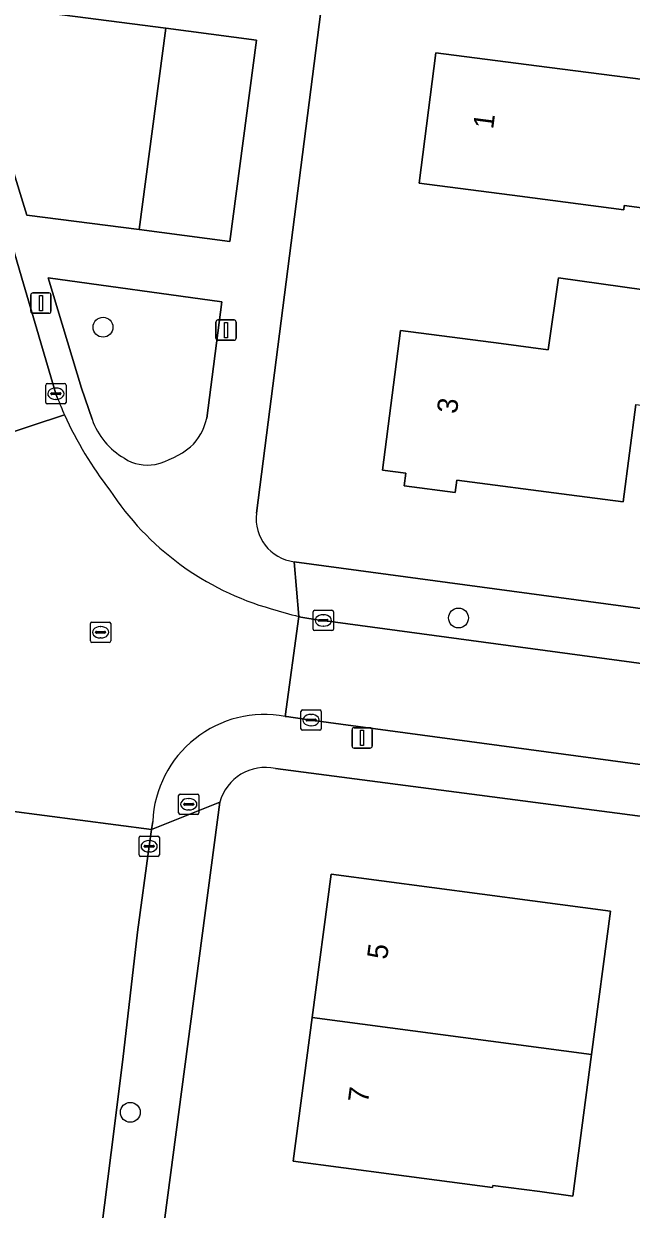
# Model space of a CAD drawing. Extents: x 161258 to 161838, y 380833 to 381727.
# Drawn here: x 161576.9 to 161606.8, y 381567.9 to 381626.2 of the extents above; entities that cross this region are included whole.
import ezdxf

# ---------------------------------------------------------------- set-up
doc = ezdxf.new("R2010")
doc.units = 0
for name, color, linetype in [('IMGEO_Boom', 7, 'Continuous'), ('IMGEO_Brandkraan', 7, 'Continuous'), ('IMGEO_Erf', 7, 'Continuous'), ('IMGEO_Groenvoorziening', 7, 'Continuous'), ('IMGEO_Kolk', 7, 'Continuous'), ('IMGEO_Lichtmast', 7, 'Continuous'), ('IMGEO_Pand', 7, 'Continuous'), ('IMGEO_Pand_nummerreeks', 7, 'Continuous'), ('IMGEO_Rijbaan_lokaal_open', 7, 'Continuous'), ('IMGEO_Rioolput', 7, 'Continuous'), ('IMGEO_Voetpad_open', 7, 'Continuous')]:
    doc.layers.add(name, color=color, linetype=linetype)

msp = doc.modelspace()

# ---------------------------------------------------------------- linework, layer by layer
at = {"layer": 'IMGEO_Boom'}
for centre in [(161580.761, 381611.263), (161598.266, 381596.955), (161582.105, 381572.63)]:
    msp.add_circle(centre, 0.489, dxfattribs=at)
at = {"layer": 'IMGEO_Brandkraan'}
for p, q in [((161584.485, 381587.362), (161584.485, 381588.214)), ((161584.56, 381588.288), (161585.412, 381588.288)), ((161585.486, 381588.214), (161585.486, 381587.362)), ((161584.744, 381587.782), (161584.744, 381587.794)), ((161585.182, 381587.745), (161584.784, 381587.745)), ((161584.787, 381587.831), (161585.185, 381587.831)), ((161584.973, 381588.068), (161584.998, 381588.068)), ((161585.228, 381587.794), (161585.228, 381587.782)), ((161585.412, 381587.288), (161584.56, 381587.288)), ((161584.996, 381587.508), (161584.971, 381587.508))]:
    msp.add_line(p, q, dxfattribs=at)
for points in [[(161584.485, 381587.362), (161584.485, 381588.214)], [(161584.56, 381588.288), (161585.412, 381588.288)], [(161585.486, 381588.214), (161585.486, 381587.362)], [(161585.412, 381587.288), (161584.56, 381587.288)]]:
    msp.add_lwpolyline(points, dxfattribs=at)
for centre, radius, start, end in [((161584.562, 381588.212), 0.0765, 91.55205, 178.44795), ((161584.562, 381588.212), 0.0765, 91.55205, 178.44795), ((161585.41, 381588.212), 0.0765, 1.55205, 88.44795), ((161585.41, 381588.212), 0.0765, 1.55205, 88.44795), ((161584.784, 381587.791), 0.0403, 85.87752, 175.75265), ((161584.781, 381587.781), 0.0366, 178.93798, 274.71019), ((161585.185, 381587.788), 0.043, 264.86636, 352.45326), ((161585.189, 381587.793), 0.0386, 1.73085, 96.63898), ((161584.562, 381587.364), 0.0765, 181.55205, 268.44795), ((161584.562, 381587.364), 0.0765, 181.55205, 268.44795), ((161585.41, 381587.364), 0.0765, 271.55205, 358.44795), ((161585.41, 381587.364), 0.0765, 271.55205, 358.44795)]:
    msp.add_arc(centre, radius, start, end, dxfattribs=at)
for centre, major_axis, ratio, start_param, end_param in [((161584.972, 381587.788), (-0.387, 0.002), 0.722429, 4.712389, 7.853982), ((161584.997, 381587.788), (-0.39, 0.002), 0.717154, 1.570796, 4.712389)]:
    msp.add_ellipse(centre, major_axis=major_axis, ratio=ratio, start_param=start_param, end_param=end_param, dxfattribs=at)
at = {"layer": 'IMGEO_Erf'}
for points in [[(161595.863, 381660.915), (161595.221, 381655.854), (161588.317, 381602.109)], [(161608.036, 381617.043), (161606.432, 381617.251), (161606.405, 381617.045), (161601.282, 381617.709), (161596.323, 381618.351), (161597.154, 381624.772), (161602.113, 381624.129), (161610.561, 381623.035)], [(161607.003, 381607.46), (161606.383, 381602.669), (161603.711, 381603.016), (161598.187, 381603.731), (161598.109, 381603.127), (161595.584, 381603.454), (161595.666, 381604.087), (161594.523, 381604.235), (161595.411, 381611.1), (161600.364, 381610.459), (161602.69, 381610.158), (161603.185, 381613.687), (161615.69, 381611.935)], [(161590.17, 381599.725), (161613.919, 381596.521)], [(161648.507, 381581.81), (161589.258, 381589.545)], [(161586.507, 381587.885), (161574.866, 381500), (161571.884, 381477.487), (161571.043, 381470.087), (161570.912, 381467.059)]]:
    msp.add_lwpolyline(points, dxfattribs=at)
msp.add_lwpolyline([(161604.813, 381575.471), (161603.891, 381568.511), (161602.271, 381568.726), (161599.955, 381569.033), (161599.942, 381568.933), (161595.085, 381569.577), (161590.128, 381570.234), (161591.063, 381577.293), (161591.998, 381584.35), (161601.906, 381583.037), (161605.748, 381582.528)], close=True, dxfattribs=at)
for centre, radius, start, end in [((161590.443, 381601.85), 2.142, 173.04184, 262.67151), ((161588.759, 381587.262), 2.336, 77.66825, 164.54674)]:
    msp.add_arc(centre, radius, start, end, dxfattribs=at)
at = {"layer": 'IMGEO_Groenvoorziening'}
for points in [[(161583.855, 381625.976), (161573.758, 381627.282), (161573.907, 381626.814), (161577.004, 381616.778), (161582.549, 381616.063)], [(161583.855, 381625.976), (161582.549, 381616.063), (161587.013, 381615.487), (161588.317, 381625.392)]]:
    msp.add_lwpolyline(points, close=True, dxfattribs=at)
for points in [[(161586.62, 381612.512), (161578.066, 381613.694), (161579.706, 381608.266), (161580.229, 381606.732)], [(161585.866, 381606.781), (161586.62, 381612.512)]]:
    msp.add_lwpolyline(points, dxfattribs=at)
for centre, radius, start, end in [((161583.561, 381607.873), 3.522, 198.9008, 240.31569), ((161583.254, 381607.329), 2.669, 312.75506, 348.14074), ((161582.191, 381608.998), 4.629, 284.31552, 308.38987), ((161582.951, 381606.557), 2.08, 236.97374, 280.68217)]:
    msp.add_arc(centre, radius, start, end, dxfattribs=at)
at = {"layer": 'IMGEO_Kolk'}
for p, q in [((161577.939, 381607.566), (161577.939, 381608.418)), ((161578.014, 381608.492), (161578.866, 381608.492)), ((161578.241, 381608.035), (161578.639, 381608.035)), ((161578.427, 381608.272), (161578.452, 381608.272)), ((161578.94, 381608.418), (161578.94, 381607.566)), ((161578.866, 381607.492), (161578.014, 381607.492)), ((161578.198, 381607.986), (161578.198, 381607.998)), ((161578.636, 381607.949), (161578.238, 381607.949)), ((161578.45, 381607.712), (161578.425, 381607.712)), ((161578.682, 381607.998), (161578.682, 381607.986)), ((161591.109, 381596.407), (161591.109, 381597.259)), ((161591.184, 381597.333), (161592.036, 381597.333)), ((161591.597, 381597.113), (161591.622, 381597.113)), ((161592.11, 381597.259), (161592.11, 381596.407)), ((161591.368, 381596.827), (161591.368, 381596.839)), ((161591.806, 381596.79), (161591.408, 381596.79)), ((161591.411, 381596.876), (161591.809, 381596.876)), ((161591.62, 381596.553), (161591.595, 381596.553)), ((161591.852, 381596.839), (161591.852, 381596.827)), ((161592.036, 381596.333), (161591.184, 381596.333)), ((161590.507, 381591.505), (161590.507, 381592.357)), ((161590.582, 381592.431), (161591.434, 381592.431)), ((161591.508, 381592.357), (161591.508, 381591.505)), ((161590.766, 381591.925), (161590.766, 381591.937)), ((161591.204, 381591.888), (161590.806, 381591.888)), ((161590.809, 381591.974), (161591.207, 381591.974)), ((161590.995, 381592.211), (161591.02, 381592.211)), ((161591.25, 381591.937), (161591.25, 381591.925)), ((161591.434, 381591.431), (161590.582, 381591.431)), ((161591.018, 381591.651), (161590.993, 381591.651)), ((161582.534, 381585.295), (161582.534, 381586.147)), ((161582.609, 381586.221), (161583.461, 381586.221)), ((161583.022, 381586.001), (161583.047, 381586.001)), ((161583.535, 381586.147), (161583.535, 381585.295)), ((161582.793, 381585.715), (161582.793, 381585.727)), ((161583.231, 381585.678), (161582.833, 381585.678)), ((161582.836, 381585.764), (161583.234, 381585.764)), ((161583.045, 381585.441), (161583.02, 381585.441)), ((161583.277, 381585.727), (161583.277, 381585.715)), ((161583.461, 381585.221), (161582.609, 381585.221))]:
    msp.add_line(p, q, dxfattribs=at)
for points in [[(161577.939, 381607.566), (161577.939, 381608.418)], [(161578.014, 381608.492), (161578.866, 381608.492)], [(161578.94, 381608.418), (161578.94, 381607.566)], [(161578.866, 381607.492), (161578.014, 381607.492)], [(161591.109, 381596.407), (161591.109, 381597.259)], [(161591.184, 381597.333), (161592.036, 381597.333)], [(161592.11, 381597.259), (161592.11, 381596.407)], [(161592.036, 381596.333), (161591.184, 381596.333)], [(161590.507, 381591.505), (161590.507, 381592.357)], [(161590.582, 381592.431), (161591.434, 381592.431)], [(161591.508, 381592.357), (161591.508, 381591.505)], [(161591.434, 381591.431), (161590.582, 381591.431)], [(161582.534, 381585.295), (161582.534, 381586.147)], [(161582.609, 381586.221), (161583.461, 381586.221)], [(161583.535, 381586.147), (161583.535, 381585.295)], [(161583.461, 381585.221), (161582.609, 381585.221)]]:
    msp.add_lwpolyline(points, dxfattribs=at)
for centre, radius, start, end in [((161578.016, 381608.416), 0.0765, 91.55205, 178.44795), ((161578.016, 381608.416), 0.0765, 91.55205, 178.44795), ((161578.238, 381607.995), 0.0403, 85.87752, 175.75265), ((161578.643, 381607.997), 0.0386, 1.73085, 96.63898), ((161578.864, 381608.416), 0.0765, 1.55205, 88.44795), ((161578.864, 381608.416), 0.0765, 1.55205, 88.44795), ((161578.016, 381607.568), 0.0765, 181.55205, 268.44795), ((161578.016, 381607.568), 0.0765, 181.55205, 268.44795), ((161578.235, 381607.985), 0.0366, 178.93798, 274.71019), ((161578.639, 381607.992), 0.043, 264.86636, 352.45326), ((161578.864, 381607.568), 0.0765, 271.55205, 358.44795), ((161578.864, 381607.568), 0.0765, 271.55205, 358.44795), ((161591.186, 381597.257), 0.0765, 91.55205, 178.44795), ((161591.186, 381597.257), 0.0765, 91.55205, 178.44795), ((161592.034, 381597.257), 0.0765, 1.55205, 88.44795), ((161592.034, 381597.257), 0.0765, 1.55205, 88.44795), ((161591.186, 381596.409), 0.0765, 181.55205, 268.44795), ((161591.186, 381596.409), 0.0765, 181.55205, 268.44795), ((161591.408, 381596.836), 0.0403, 85.87752, 175.75265), ((161591.405, 381596.826), 0.0366, 178.93798, 274.71019), ((161591.809, 381596.833), 0.043, 264.86636, 352.45326), ((161591.813, 381596.838), 0.0386, 1.73085, 96.63898), ((161592.034, 381596.409), 0.0765, 271.55205, 358.44795), ((161592.034, 381596.409), 0.0765, 271.55205, 358.44795), ((161590.584, 381592.355), 0.0765, 91.55205, 178.44795), ((161590.584, 381592.355), 0.0765, 91.55205, 178.44795), ((161591.432, 381592.355), 0.0765, 1.55205, 88.44795), ((161591.432, 381592.355), 0.0765, 1.55205, 88.44795), ((161590.806, 381591.934), 0.0403, 85.87752, 175.75265), ((161590.803, 381591.924), 0.0366, 178.93798, 274.71019), ((161591.207, 381591.931), 0.043, 264.86636, 352.45326), ((161591.211, 381591.936), 0.0386, 1.73085, 96.63898), ((161590.584, 381591.507), 0.0765, 181.55205, 268.44795), ((161590.584, 381591.507), 0.0765, 181.55205, 268.44795), ((161591.432, 381591.507), 0.0765, 271.55205, 358.44795), ((161591.432, 381591.507), 0.0765, 271.55205, 358.44795), ((161582.611, 381586.145), 0.0765, 91.55205, 178.44795), ((161582.611, 381586.145), 0.0765, 91.55205, 178.44795), ((161583.459, 381586.145), 0.0765, 1.55205, 88.44795), ((161583.459, 381586.145), 0.0765, 1.55205, 88.44795), ((161582.611, 381585.297), 0.0765, 181.55205, 268.44795), ((161582.611, 381585.297), 0.0765, 181.55205, 268.44795), ((161582.833, 381585.724), 0.0403, 85.87752, 175.75265), ((161582.83, 381585.714), 0.0366, 178.93798, 274.71019), ((161583.234, 381585.721), 0.043, 264.86636, 352.45326), ((161583.238, 381585.726), 0.0386, 1.73085, 96.63898), ((161583.459, 381585.297), 0.0765, 271.55205, 358.44795), ((161583.459, 381585.297), 0.0765, 271.55205, 358.44795)]:
    msp.add_arc(centre, radius, start, end, dxfattribs=at)
for centre, major_axis, ratio, start_param, end_param in [((161578.426, 381607.992), (-0.387, 0.002), 0.722429, 4.712389, 7.853982), ((161578.451, 381607.992), (-0.39, 0.002), 0.717154, 1.570796, 4.712389), ((161591.596, 381596.833), (-0.387, 0.002), 0.722429, 4.712389, 7.853982), ((161591.621, 381596.833), (-0.39, 0.002), 0.717154, 1.570796, 4.712389), ((161590.994, 381591.931), (-0.387, 0.002), 0.722429, 4.712389, 7.853982), ((161591.019, 381591.931), (-0.39, 0.002), 0.717154, 1.570796, 4.712389), ((161583.021, 381585.721), (-0.387, 0.002), 0.722429, 4.712389, 7.853982), ((161583.046, 381585.721), (-0.39, 0.002), 0.717154, 1.570796, 4.712389)]:
    msp.add_ellipse(centre, major_axis=major_axis, ratio=ratio, start_param=start_param, end_param=end_param, dxfattribs=at)
at = {"layer": 'IMGEO_Lichtmast'}
for p, q in [((161577.207, 381612.049), (161577.207, 381612.849)), ((161577.207, 381612.849), (161577.207, 381612.049)), ((161577.307, 381612.949), (161578.097, 381612.949)), ((161578.097, 381612.949), (161577.307, 381612.949)), ((161578.197, 381612.849), (161578.197, 381612.049)), ((161578.197, 381612.049), (161578.197, 381612.849)), ((161578.097, 381611.949), (161577.307, 381611.949)), ((161577.307, 381611.949), (161578.097, 381611.949)), ((161586.322, 381610.718), (161586.322, 381611.518)), ((161586.322, 381611.518), (161586.322, 381610.718)), ((161586.422, 381611.618), (161587.212, 381611.618)), ((161587.212, 381611.618), (161586.422, 381611.618)), ((161587.312, 381611.518), (161587.312, 381610.718)), ((161587.312, 381610.718), (161587.312, 381611.518)), ((161587.212, 381610.618), (161586.422, 381610.618)), ((161586.422, 381610.618), (161587.212, 381610.618)), ((161593.025, 381590.655), (161593.025, 381591.455)), ((161593.025, 381591.455), (161593.025, 381590.655)), ((161593.125, 381591.555), (161593.915, 381591.555)), ((161593.915, 381591.555), (161593.125, 381591.555)), ((161594.015, 381591.455), (161594.015, 381590.655)), ((161594.015, 381590.655), (161594.015, 381591.455)), ((161593.915, 381590.555), (161593.125, 381590.555)), ((161593.125, 381590.555), (161593.915, 381590.555))]:
    msp.add_line(p, q, dxfattribs=at)
for points in [[(161577.627, 381612.824), (161577.777, 381612.824), (161577.777, 381612.074), (161577.627, 381612.074), (161577.627, 381612.824)], [(161586.742, 381611.493), (161586.892, 381611.493), (161586.892, 381610.743), (161586.742, 381610.743), (161586.742, 381611.493)], [(161593.445, 381591.43), (161593.595, 381591.43), (161593.595, 381590.68), (161593.445, 381590.68), (161593.445, 381591.43)]]:
    msp.add_lwpolyline(points, dxfattribs=at)
for centre, start, end in [((161577.307, 381612.849), 90, 180), ((161577.307, 381612.849), 90, 180), ((161578.097, 381612.849), 0, 90), ((161578.097, 381612.849), 360, 90), ((161577.307, 381612.049), 180, 270), ((161577.307, 381612.049), 180, 270), ((161578.097, 381612.049), 270, 0), ((161578.097, 381612.049), 270, 0), ((161586.422, 381611.518), 90, 180), ((161586.422, 381611.518), 90, 180), ((161587.212, 381611.518), 0, 90), ((161587.212, 381611.518), 360, 90), ((161586.422, 381610.718), 180, 270), ((161586.422, 381610.718), 180, 270), ((161587.212, 381610.718), 270, 0), ((161587.212, 381610.718), 270, 0), ((161593.125, 381591.455), 90, 180), ((161593.125, 381591.455), 90, 180), ((161593.915, 381591.455), 0, 90), ((161593.915, 381591.455), 360, 90), ((161593.125, 381590.655), 180, 270), ((161593.125, 381590.655), 180, 270), ((161593.915, 381590.655), 270, 0), ((161593.915, 381590.655), 270, 0)]:
    msp.add_arc(centre, 0.1, start, end, dxfattribs=at)
at = {"layer": 'IMGEO_Pand'}
for points in [[(161610.425, 381622.043), (161610.561, 381623.035), (161602.113, 381624.129), (161597.154, 381624.772), (161596.323, 381618.351), (161601.282, 381617.709), (161606.405, 381617.045), (161606.432, 381617.251), (161608.036, 381617.043), (161608.278, 381620.285), (161608.452, 381620.262), (161609.713, 381620.099), (161609.999, 381620.062), (161610.173, 381620.039)], [(161607.003, 381607.46), (161613.628, 381606.602), (161614.838, 381606.445), (161615.239, 381606.393), (161616.042, 381611.886), (161615.69, 381611.935), (161603.185, 381613.687), (161602.69, 381610.158), (161600.364, 381610.459), (161595.411, 381611.1), (161594.523, 381604.235), (161595.666, 381604.087), (161595.584, 381603.454), (161598.109, 381603.127), (161598.187, 381603.731), (161603.711, 381603.016), (161606.383, 381602.669)], [(161604.813, 381575.471), (161605.748, 381582.528), (161601.906, 381583.037), (161591.998, 381584.35), (161591.063, 381577.293)], [(161604.813, 381575.471), (161591.063, 381577.293), (161590.128, 381570.234), (161595.085, 381569.577), (161599.942, 381568.933), (161599.955, 381569.033), (161602.271, 381568.726), (161603.891, 381568.511)]]:
    msp.add_lwpolyline(points, close=True, dxfattribs=at)
at = {"layer": 'IMGEO_Rijbaan_lokaal_open'}
for points in [[(161561.573, 381639.633), (161562.515, 381636.554), (161564.251, 381630.676), (161567.807, 381619.07), (161571.743, 381606.032), (161572.129, 381604.736), (161578.866, 381606.95)], [(161578.509, 381607.801), (161578.44, 381607.992), (161576.757, 381613.681), (161575.68, 381617.326), (161575.658, 381617.399), (161572.869, 381626.513), (161571.465, 381631.202)], [(161578.866, 381606.95), (161572.129, 381604.736), (161573.019, 381601.753), (161574.017, 381598.214), (161575.532, 381593.296)], [(161614.689, 381593.717), (161591.61, 381596.833), (161591.3, 381596.865), (161590.603, 381596.979), (161590.506, 381597.003), (161590.41, 381597.026), (161589.729, 381592.114), (161589.764, 381592.108), (161589.798, 381592.101), (161591.008, 381591.931), (161614.153, 381588.812)], [(161589.729, 381592.114), (161590.41, 381597.026)], [(161580.345, 381564.178), (161581.163, 381570.648), (161581.742, 381575.234), (161582.456, 381581.501), (161583.035, 381585.721), (161583.151, 381586.547), (161576.131, 381587.471), (161576.004, 381586.446), (161575.751, 381584.539), (161575.172, 381580.435), (161574.137, 381572.407), (161572.882, 381563.041)], [(161576.131, 381587.471), (161583.151, 381586.547), (161583.208, 381586.948)]]:
    msp.add_lwpolyline(points, dxfattribs=at)
for centre, radius, start, end in [((161594.941, 381614.194), 17.631, 201.25873, 204.258), ((161595.257, 381614.313), 17.969, 204.18841, 218.00729), ((161592.876, 381610.942), 14.068, 213.15639, 254.19601), ((161597.007, 381623.363), 27.151, 252.94823, 255.93862), ((161588.718, 381586.692), 5.516, 79.43645, 177.33677)]:
    msp.add_arc(centre, radius, start, end, dxfattribs=at)
at = {"layer": 'IMGEO_Rioolput'}
for p, q in [((161580.14, 381595.825), (161580.14, 381596.677)), ((161580.215, 381596.751), (161581.067, 381596.751)), ((161580.628, 381596.531), (161580.653, 381596.531)), ((161581.141, 381596.677), (161581.141, 381595.825)), ((161580.399, 381596.245), (161580.399, 381596.257)), ((161580.837, 381596.208), (161580.439, 381596.208)), ((161580.442, 381596.294), (161580.84, 381596.294)), ((161580.651, 381595.971), (161580.626, 381595.971)), ((161580.883, 381596.257), (161580.883, 381596.245)), ((161581.067, 381595.751), (161580.215, 381595.751))]:
    msp.add_line(p, q, dxfattribs=at)
for points in [[(161580.14, 381595.825), (161580.14, 381596.677)], [(161580.215, 381596.751), (161581.067, 381596.751)], [(161581.141, 381596.677), (161581.141, 381595.825)], [(161581.067, 381595.751), (161580.215, 381595.751)]]:
    msp.add_lwpolyline(points, dxfattribs=at)
for centre, radius, start, end in [((161580.217, 381596.675), 0.0765, 91.55205, 178.44795), ((161580.217, 381596.675), 0.0765, 91.55205, 178.44795), ((161581.065, 381596.675), 0.0765, 1.55205, 88.44795), ((161581.065, 381596.675), 0.0765, 1.55205, 88.44795), ((161580.217, 381595.827), 0.0765, 181.55205, 268.44795), ((161580.217, 381595.827), 0.0765, 181.55205, 268.44795), ((161580.439, 381596.254), 0.0403, 85.87752, 175.75265), ((161580.436, 381596.244), 0.0366, 178.93798, 274.71019), ((161580.84, 381596.251), 0.043, 264.86636, 352.45326), ((161580.844, 381596.256), 0.0386, 1.73085, 96.63898), ((161581.065, 381595.827), 0.0765, 271.55205, 358.44795), ((161581.065, 381595.827), 0.0765, 271.55205, 358.44795)]:
    msp.add_arc(centre, radius, start, end, dxfattribs=at)
for centre, major_axis, ratio, start_param, end_param in [((161580.627, 381596.251), (-0.387, 0.002), 0.722429, 4.712389, 7.853982), ((161580.652, 381596.251), (-0.39, 0.002), 0.717154, 1.570796, 4.712389)]:
    msp.add_ellipse(centre, major_axis=major_axis, ratio=ratio, start_param=start_param, end_param=end_param, dxfattribs=at)
at = {"layer": 'IMGEO_Voetpad_open'}
for points in [[(161588.317, 381602.109), (161595.221, 381655.854)], [(161568.808, 381643.777), (161567.509, 381644.155), (161568.587, 381640.639), (161569.751, 381636.854), (161571.308, 381631.795), (161571.465, 381631.202), (161572.869, 381626.513), (161575.658, 381617.399), (161575.68, 381617.326), (161576.757, 381613.681), (161578.44, 381607.992), (161578.509, 381607.801)], [(161580.229, 381606.732), (161579.706, 381608.266), (161578.066, 381613.694), (161586.62, 381612.512)], [(161586.62, 381612.512), (161585.866, 381606.781)], [(161590.41, 381597.026), (161590.17, 381599.725)], [(161646.629, 381584.448), (161644.429, 381584.771), (161619.122, 381588.157), (161617.916, 381588.319), (161614.153, 381588.812), (161591.008, 381591.931), (161589.798, 381592.101), (161589.764, 381592.108), (161589.729, 381592.114)], [(161589.258, 381589.545), (161648.507, 381581.81), (161648.68, 381581.562), (161654.227, 381580.806), (161654.253, 381581.004), (161697.263, 381575.097), (161697.567, 381575.055), (161697.936, 381577.548), (161697.62, 381577.589), (161697.6, 381577.592), (161683.665, 381579.482), (161662.594, 381582.337), (161656.447, 381583.147), (161646.629, 381584.448)], [(161569.179, 381453.691), (161571.043, 381470.087), (161571.884, 381477.487), (161574.866, 381500), (161586.507, 381587.885)], [(161586.507, 381587.885), (161583.151, 381586.547), (161583.035, 381585.721), (161582.456, 381581.501), (161581.742, 381575.234), (161581.163, 381570.648), (161580.345, 381564.178), (161578.342, 381549.389), (161577.269, 381541.528), (161576.585, 381536.522), (161575.385, 381527.238), (161574.905, 381523.52), (161574.519, 381520.584), (161573.416, 381512.187), (161572.723, 381506.947), (161571.805, 381500)], [(161583.208, 381586.948), (161583.151, 381586.547), (161586.507, 381587.885)]]:
    msp.add_lwpolyline(points, dxfattribs=at)
for points in [[(161582.549, 381616.063), (161577.004, 381616.778), (161573.907, 381626.814), (161573.758, 381627.282), (161583.855, 381625.976), (161588.317, 381625.392), (161587.013, 381615.487)], [(161615.118, 381596.359), (161613.919, 381596.521), (161590.17, 381599.725), (161590.41, 381597.026), (161590.506, 381597.003), (161590.603, 381596.979), (161591.3, 381596.865), (161591.61, 381596.833), (161614.689, 381593.717), (161618.426, 381593.228), (161618.458, 381593.224), (161619.675, 381593.074), (161645.071, 381589.627), (161663.266, 381587.166), (161684.368, 381584.359), (161706.756, 381581.348), (161707.156, 381581.295), (161707.511, 381583.893), (161707.085, 381583.95)]]:
    msp.add_lwpolyline(points, close=True, dxfattribs=at)
for centre, radius, start, end in [((161594.941, 381614.194), 17.631, 201.25873, 204.258), ((161595.257, 381614.313), 17.969, 204.18841, 218.00729), ((161583.561, 381607.873), 3.522, 198.9008, 240.31569), ((161583.254, 381607.329), 2.669, 312.75506, 348.14074), ((161582.191, 381608.998), 4.629, 284.31552, 308.38987), ((161582.951, 381606.557), 2.08, 236.97374, 280.68217), ((161592.876, 381610.942), 14.068, 213.15639, 254.19601), ((161590.443, 381601.85), 2.142, 173.04184, 262.67151), ((161597.007, 381623.363), 27.151, 252.94823, 255.93862), ((161588.718, 381586.692), 5.516, 79.43645, 177.33677), ((161588.759, 381587.262), 2.336, 77.66825, 164.54674)]:
    msp.add_arc(centre, radius, start, end, dxfattribs=at)

# ---------------------------------------------------------------- texts
at = {"layer": 'IMGEO_Pand_nummerreeks'}
for s, rotation, p in [('1', 82.62624, (161599.971, 381620.98)), ('3', 82.63197, (161598.185, 381606.973)), ('5', 82.45375, (161594.746, 381580.117)), ('7', 82.45375, (161593.811, 381573.059))]:
    msp.add_text(s, height=1, rotation=rotation, dxfattribs=at).set_placement(p)

doc.saveas('drawing.dxf')
